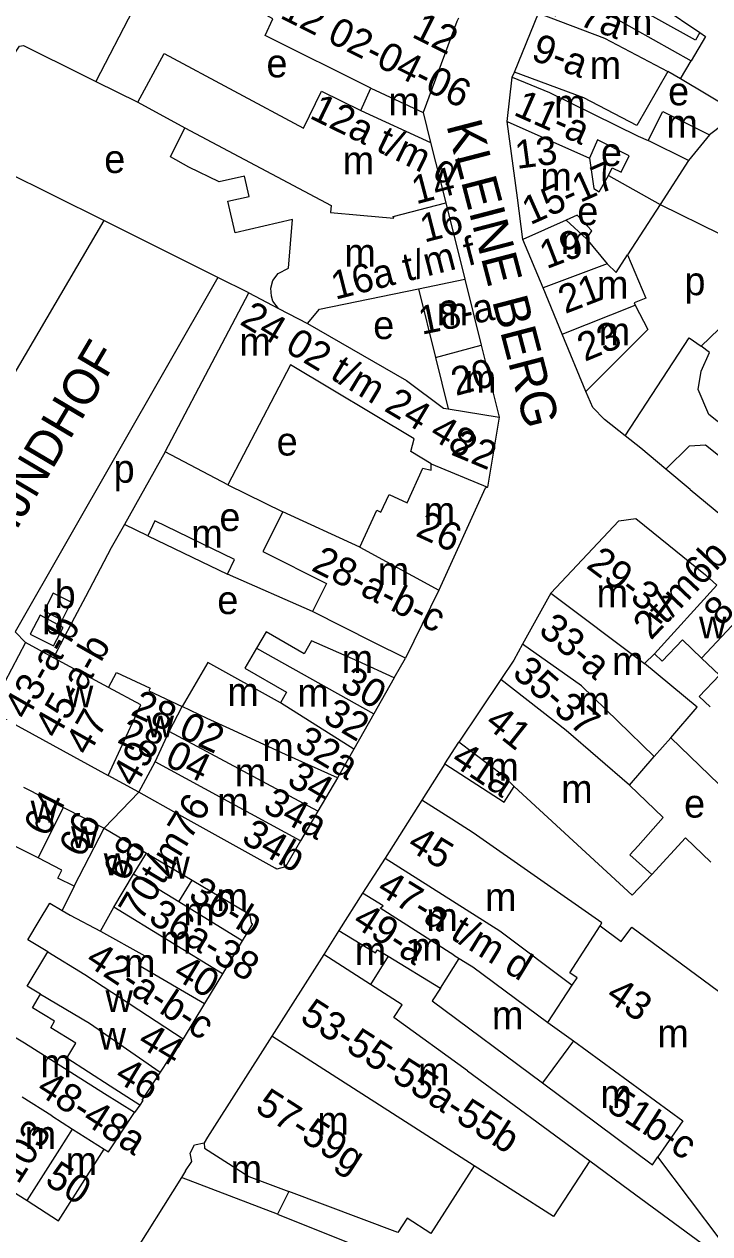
# Model space of a CAD drawing. Extents: x 160673 to 161924, y 382258 to 384145.
# Drawn here: x 161061.5 to 161158.4, y 383019.8 to 383190.7 of the extents above; entities that cross this region are included whole.
import ezdxf

# ---------------------------------------------------------------- set-up
doc = ezdxf.new("R2010")
doc.units = 0
for name, color, linetype in [('BLT_Basislijn', 7, 'Continuous'), ('BLT_Bebouwing', 7, 'Continuous'), ('BLT_Centroide', 7, 'Continuous'), ('BLT_Huisnummer', 7, 'Continuous'), ('BLT_Huisnummer_ tussenligend', 7, 'Continuous'), ('BLT_Huisnummer_reeks', 7, 'Continuous'), ('BLT_Onderdoorgang_en_onderverdeling', 7, 'Continuous'), ('BLT_Onderverdeling_panden', 7, 'Continuous'), ('BLT_Straatnaam', 7, 'Continuous'), ('BLT_Vlakafsluiter', 7, 'Continuous')]:
    doc.layers.add(name, color=color, linetype=linetype)

msp = doc.modelspace()

# ---------------------------------------------------------------- linework, layer by layer
at = {"layer": 'BLT_Basislijn'}
for p, q in [((161076.84, 383192.65), (161071.59, 383182.56)), ((161130.49, 383183.2), (161130.79, 383183.88)), ((161071.59, 383182.56), (161077.56, 383179.63)), ((161072.75, 383162.91), (161058.69, 383169.92)), ((161088.85, 383154.88), (161072.75, 383162.91)), ((161093.23, 383152.7), (161088.85, 383154.88)), ((161157.21, 383145.16), (161166.57, 383154.31)), ((161146.44, 383132.53), (161155.48, 383146.36)), ((161155.48, 383146.36), (161157.21, 383145.16)), ((161158.39, 383144.3), (161157.21, 383145.16)), ((161081.4, 383130.24), (161075.65, 383120.01)), ((161152.18, 383127.82), (161155.52, 383131.12)), ((161090.28, 383125.58), (161098.04, 383121.78)), ((161075.65, 383120.01), (161073.77, 383116.67)), ((161078.95, 383118.39), (161075.65, 383120.01)), ((161073.77, 383116.67), (161070.15, 383109.78)), ((161102.23, 383107.69), (161090.22, 383112.96)), ((161066.27, 383102.41), (161065.61, 383101.15)), ((161113.8, 383098.31), (161115.37, 383101.09)), ((161161.04, 383082.01), (161152.88, 383089.86)), ((161120.94, 383086.18), (161117.7, 383081.03)), ((161077.83, 383037.95), (161077.07, 383036.91)), ((161141.47, 383030.08), (161147.07, 383025.97)), ((161083.7, 383027.74), (161075.08, 383013.99)), ((161097.27, 383022.58), (161108.71, 383018))]:
    msp.add_line(p, q, dxfattribs=at)
for points in [[(161051.19, 383173.08), (161060.81, 383187.57), (161061.4, 383187.65), (161069.83, 383183.47), (161071.59, 383182.56)], [(161162.43, 383178.08), (161158.35, 383175.04)], [(161155.39, 383171.39), (161151.4, 383165.2)], [(161151.4, 383165.2), (161159.81, 383161.05)], [(161072.75, 383162.91), (161043.52, 383113.14), (161040.44, 383114.74)], [(161209.41, 383155.55), (161179.71, 383126.22), (161175.81, 383125.09), (161170.52, 383125.84), (161158.26, 383135.53), (161156.75, 383139.06), (161157.19, 383141.64), (161158.39, 383144.3)], [(161088.85, 383154.88), (161060.21, 383104.82), (161061.64, 383103.3)], [(161146.44, 383132.53), (161143.53, 383134.81), (161141.88, 383136.5), (161140.88, 383138.76)], [(161152.18, 383127.82), (161148.65, 383130.79), (161146.44, 383132.53)], [(161155.52, 383131.12), (161157.8, 383131.22), (161161.28, 383128.45)], [(161155.64, 383124.92), (161152.18, 383127.82)], [(161155.64, 383124.92), (161164.31, 383117.78), (161166.06, 383116.33)], [(161070.15, 383109.78), (161068.6, 383106.83), (161066.57, 383102.99)], [(161066.57, 383102.99), (161066.27, 383102.41)], [(161150.23, 383070.53), (161154.97, 383075.72), (161158.54, 383072.29)], [(161147.07, 383025.97), (161159.71, 383016.67), (161164.6, 383021.65), (161166.91, 383019.35)]]:
    msp.add_lwpolyline(points, dxfattribs=at)
at = {"layer": 'BLT_Bebouwing'}
for p, q in [((161130.79, 383183.88), (161134.17, 383192.23)), ((161129.78, 383176.9), (161130.49, 383183.2)), ((161154.26, 383182.93), (161152.49, 383183.98)), ((161162.43, 383178.08), (161154.26, 383182.93)), ((161109.06, 383178.49), (161110.48, 383181.61)), ((161077.56, 383179.63), (161084.17, 383176.03)), ((161117.87, 383178.2), (161118.94, 383173.94)), ((161131.21, 383166.12), (161129.78, 383176.9)), ((161148.26, 383174.86), (161149.71, 383174.23)), ((161158.35, 383175.04), (161155.39, 383171.39)), ((161118.94, 383173.94), (161121.07, 383165.43)), ((161131.98, 383160.27), (161131.21, 383166.12)), ((161121.07, 383165.43), (161123.77, 383154.64)), ((161151.4, 383165.2), (161146.78, 383158.1)), ((161138.1, 383163), (161140.96, 383160.36)), ((161134.83, 383153.4), (161131.98, 383160.27)), ((161123.77, 383154.64), (161126.09, 383145.34)), ((161088.98, 383144.64), (161093.23, 383152.7)), ((161093.23, 383152.7), (161097.43, 383150.49)), ((161117.21, 383153.29), (161119.61, 383143.57)), ((161137.52, 383146.87), (161134.83, 383153.4)), ((161140.88, 383138.76), (161137.52, 383146.87)), ((161126.09, 383145.34), (161128.64, 383135.15)), ((161081.4, 383130.24), (161088.98, 383144.64)), ((161119.61, 383143.57), (161121.4, 383136.32)), ((161099.14, 383142.56), (161090.28, 383125.58)), ((161128.64, 383135.15), (161126.98, 383125.25)), ((161090.28, 383125.58), (161081.4, 383130.24)), ((161108.95, 383116.78), (161098.04, 383121.78)), ((161078.95, 383118.39), (161090.22, 383112.96)), ((161061.64, 383103.3), (161056.57, 383093.7)), ((161065.61, 383101.15), (161061.64, 383103.3)), ((161149.17, 383100.36), (161150.57, 383101.73)), ((161128.87, 383098.07), (161125.92, 383093.68)), ((161056.57, 383093.7), (161073.37, 383084.54)), ((161110.9, 383093.25), (161108.06, 383088.27)), ((161125.92, 383093.68), (161122.93, 383089.24)), ((161120.94, 383086.18), (161122.93, 383089.24)), ((161150.56, 383087.2), (161152.88, 383089.86)), ((161108.06, 383088.27), (161105.75, 383084.22)), ((161147.05, 383083.15), (161150.56, 383087.2)), ((161077.68, 383082.16), (161073.37, 383084.54)), ((161061.39, 383082.87), (161067.01, 383080.02)), ((161083.39, 383078.96), (161077.68, 383082.16)), ((161117.7, 383081.03), (161112.5, 383072.87)), ((161072.76, 383077.1), (161078.78, 383073.57)), ((161063.43, 383072.88), (161057.76, 383075.74)), ((161078.78, 383073.57), (161085.22, 383069.75)), ((161112.5, 383072.87), (161109.33, 383067.89)), ((161068.55, 383068.88), (161066.83, 383065.47)), ((161109.33, 383067.89), (161105.98, 383062.63)), ((161105.98, 383062.63), (161103.83, 383059.25)), ((161092.31, 383061.17), (161089.51, 383056.53)), ((161103.83, 383059.25), (161096.48, 383047.7)), ((161112.95, 383058.99), (161110.43, 383055.02)), ((161112.95, 383058.99), (161120.33, 383054.5)), ((161089.51, 383056.53), (161086.96, 383052.3)), ((161086.96, 383052.3), (161083.96, 383047.34)), ((161124.16, 383042.8), (161141.47, 383030.08)), ((161054.77, 383028.99), (161061.89, 383024.47)), ((161084.29, 383028.68), (161083.7, 383027.74)), ((161097.27, 383022.58), (161083.7, 383027.74)), ((161098.9, 383025.78), (161097.27, 383022.58)), ((161114.31, 383019.97), (161098.9, 383025.78))]:
    msp.add_line(p, q, dxfattribs=at)
for points in [[(161110.48, 383181.61), (161095.55, 383189.07), (161096.62, 383191.43), (161080.88, 383200.25)], [(161122.86, 383191.51), (161122.64, 383191.04), (161117.87, 383178.2)], [(161077.56, 383179.63), (161081.25, 383186.53), (161100.96, 383175.99), (161103.5, 383181.21), (161109.06, 383178.49)], [(161130.49, 383183.2), (161135.76, 383181.02), (161148.26, 383174.86)], [(161152.49, 383183.98), (161148.1, 383176.35), (161140.59, 383180.25), (161130.79, 383183.88)], [(161149.71, 383174.23), (161151.76, 383178.33), (161158.35, 383175.04)], [(161099.42, 383163.07), (161091.31, 383161.2), (161090.27, 383165.64), (161093.27, 383166.34), (161092.61, 383169.21), (161089.04, 383168.38), (161084.73, 383170.48), (161082.17, 383171.92), (161084.17, 383176.03)], [(161144.07, 383169.29), (161144.63, 383170.37), (161145.89, 383169.76), (161146.99, 383172.05), (161142.52, 383174.32), (161141.42, 383171.74)], [(161155.39, 383171.39), (161149.71, 383174.23)], [(161141.42, 383171.74), (161142.03, 383167.45), (161142.77, 383166.98), (161144.07, 383169.29)], [(161144.07, 383169.29), (161151.4, 383165.2)], [(161097.43, 383150.49), (161096.64, 383151.55), (161096.42, 383152.24), (161096.36, 383153.39), (161096.65, 383154.47), (161097.38, 383155.45), (161098.84, 383156.2), (161099.42, 383163.07)], [(161140.96, 383160.36), (161141.73, 383161.47), (161139.65, 383163.67), (161138.1, 383163)], [(161146.78, 383158.1), (161149.39, 383151.96), (161147.71, 383151.31), (161147.88, 383150.98)], [(161101.53, 383148.39), (161103.25, 383150.41), (161117.21, 383153.29)], [(161147.88, 383150.98), (161149.64, 383147.54)], [(161101.53, 383148.39), (161115.54, 383140.31), (161120.75, 383136.43), (161121.4, 383136.32)], [(161149.64, 383147.54), (161140.88, 383138.76)], [(161116.6, 383132.1), (161099.14, 383142.56)], [(161119.03, 383128.58), (161116.15, 383130.3), (161116.6, 383132.1)], [(161108.95, 383116.78), (161111.35, 383122), (161111.92, 383121.74), (161113.06, 383124.23), (161115.61, 383123.06), (161117.85, 383127.93), (161119.01, 383127.65), (161119.03, 383128.58)], [(161126.98, 383125.25), (161126.63, 383125.12), (161120.12, 383110.73)], [(161098.04, 383121.78), (161095.23, 383116.18), (161104.23, 383111.66), (161102.23, 383107.69)], [(161090.22, 383112.96), (161091.23, 383115.06), (161079.96, 383120.49), (161078.95, 383118.39)], [(161135.95, 383110.3), (161145.53, 383120.49), (161147.95, 383120.82), (161150.4, 383118.88), (161157.82, 383112.89), (161159.39, 383111.43)], [(161120.12, 383110.73), (161115.37, 383101.09)], [(161135.95, 383110.3), (161131.91, 383103.09)], [(161115.37, 383101.09), (161110.9, 383103.33), (161102.23, 383107.69)], [(161113.8, 383098.31), (161108.65, 383100.67), (161102.12, 383103.56), (161101.06, 383101.73), (161095.67, 383104.84), (161094.32, 383102.5)], [(161094.32, 383102.5), (161092.68, 383099.68), (161098.57, 383096.28), (161097.72, 383094.8)], [(161131.91, 383103.09), (161130.7, 383100.84), (161128.87, 383098.07)], [(161150.57, 383101.73), (161151.68, 383100.68), (161154.55, 383103.7), (161157.26, 383101.11)], [(161073.39, 383096.95), (161065.61, 383101.15)], [(161157.26, 383101.11), (161159.79, 383098.71), (161156.9, 383095.68), (161158.44, 383094.23)], [(161073.39, 383096.95), (161074.54, 383099.08), (161079.29, 383096.87), (161079.11, 383096.49), (161083.81, 383094.3)], [(161097.72, 383094.8), (161087.46, 383100.48), (161083.81, 383094.3)], [(161152.88, 383089.86), (161156.62, 383094.17), (161149.17, 383100.36)], [(161113.8, 383098.31), (161111.93, 383095.06), (161110.9, 383093.25)], [(161120.94, 383086.18), (161129.32, 383080.76), (161130.76, 383082.98)], [(161105.75, 383084.22), (161102.97, 383079.48)], [(161130.76, 383082.98), (161147.45, 383067.64), (161150.23, 383070.53)], [(161148.26, 383074.59), (161151.83, 383078.62), (161147.05, 383083.15)], [(161142.9, 383063.27), (161143.15, 383063.73), (161124.96, 383076.42), (161121.92, 383078.35), (161117.7, 383081.03)], [(161067.01, 383080.02), (161072.76, 383077.1)], [(161100.55, 383075.31), (161098.4, 383071.62), (161097.2, 383071.3), (161096.94, 383071.45), (161083.39, 383078.96)], [(161102.97, 383079.48), (161100.55, 383075.31)], [(161150.23, 383070.53), (161147.12, 383073.3), (161148.26, 383074.59)], [(161068.55, 383068.88), (161066.25, 383070.04), (161066.82, 383071.18), (161063.43, 383072.88)], [(161085.22, 383069.75), (161093.35, 383064.93), (161093.59, 383063.7), (161093.77, 383063.59), (161092.31, 383061.17)], [(161064.81, 383059.61), (161061.97, 383061.32), (161063.58, 383063.99), (161065.11, 383066.51), (161066.83, 383065.47)], [(161142.9, 383063.27), (161145.9, 383061.07), (161147.38, 383063.09), (161165.58, 383049.68), (161160.36, 383042.62), (161166.42, 383034.63), (161182.45, 383049.09), (161188.86, 383040.67), (161168.78, 383025.44), (161165.52, 383026.79), (161163.14, 383021.14), (161160.04, 383018.81), (161151.05, 383030.64)], [(161063.79, 383053.62), (161061.88, 383054.75), (161064.81, 383059.61)], [(161124.16, 383042.8), (161113.74, 383050.32), (161114.93, 383052.13), (161110.43, 383055.02)], [(161120.33, 383054.5), (161119.17, 383052.68), (161134.74, 383041.1)], [(161077.83, 383037.95), (161073.63, 383040.66), (161067.5, 383044.62), (161068.78, 383046.74), (161065.22, 383048.89), (161065.78, 383049.83), (161062.65, 383051.72), (161063.79, 383053.62)], [(161077.07, 383036.91), (161072.84, 383039.57), (161061.53, 383046.73), (161051.94, 383052.4), (161048.44, 383047.22)], [(161096.48, 383047.7), (161087.39, 383033.43), (161086.9, 383032.65)], [(161083.96, 383047.34), (161083.23, 383046.12), (161083.06, 383046.22), (161080.7, 383042.63)], [(161080.7, 383042.63), (161078.1, 383038.68), (161078.23, 383038.6), (161077.83, 383037.95)], [(161134.74, 383041.1), (161150.3, 383029.52), (161151.05, 383030.64)], [(161072.77, 383031.74), (161073.39, 383031.36), (161077.07, 383036.91)], [(161084.29, 383028.68), (161085.19, 383029.99), (161084.92, 383031.18), (161085.56, 383032.36), (161086.9, 383032.65)], [(161061.89, 383024.47), (161066.34, 383021.63), (161072.77, 383031.74)], [(161125.11, 383029.37), (161118.99, 383019.85), (161115.63, 383022.01), (161114.31, 383019.97)], [(161141.47, 383030.08), (161136.3, 383022.23), (161125.11, 383029.37)]]:
    msp.add_lwpolyline(points, dxfattribs=at)
for points in [[(161064.29, 383107.78), (161066.83, 383106.48), (161068.12, 383109.02), (161065.59, 383110.31)], [(161063.72, 383107.16), (161062.34, 383104.49), (161065.62, 383102.83), (161066.97, 383105.42)]]:
    msp.add_lwpolyline(points, close=True, dxfattribs=at)
at = {"layer": 'BLT_Onderdoorgang_en_onderverdeling'}
msp.add_lwpolyline([(161086.9, 383032.65), (161086.98, 383031.9), (161093.26, 383027.9), (161098.9, 383025.78)], dxfattribs=at)
at = {"layer": 'BLT_Onderverdeling_panden'}
for p, q in [((161154.26, 383182.93), (161155.76, 383185.47)), ((161110.48, 383181.61), (161117.87, 383178.2)), ((161109.06, 383178.49), (161118.94, 383173.94)), ((161084.17, 383176.03), (161104.86, 383165.03)), ((161129.78, 383176.9), (161141.42, 383171.74)), ((161104.86, 383165.03), (161104.8, 383164.07)), ((161104.8, 383164.07), (161109, 383163.68)), ((161138.1, 383163), (161131.98, 383160.27)), ((161140.96, 383160.36), (161143.9, 383156.79)), ((161143.9, 383156.79), (161134.83, 383153.4)), ((161117.21, 383153.29), (161123.77, 383154.64)), ((161097.43, 383150.49), (161101.53, 383148.39)), ((161137.52, 383146.87), (161147.88, 383150.98)), ((161119.61, 383143.57), (161126.09, 383145.34)), ((161121.4, 383136.32), (161128.64, 383135.15)), ((161119.03, 383128.58), (161126.98, 383125.25)), ((161108.95, 383116.78), (161120.12, 383110.73)), ((161159.39, 383111.43), (161150.57, 383101.73)), ((161135.95, 383110.3), (161149.17, 383100.36)), ((161157.26, 383101.11), (161163.35, 383107.64)), ((161094.32, 383102.5), (161110.9, 383093.25)), ((161138.11, 383090.91), (161128.87, 383098.07)), ((161081.99, 383090.76), (161083.81, 383094.3)), ((161087.36, 383092.6), (161083.81, 383094.3)), ((161108.06, 383088.27), (161097.72, 383094.8)), ((161079.98, 383086.48), (161081.99, 383090.76)), ((161102.97, 383079.48), (161081.99, 383090.76)), ((161147.05, 383083.15), (161138.11, 383090.91)), ((161077.68, 383082.16), (161079.98, 383086.48)), ((161100.55, 383075.31), (161079.98, 383086.48)), ((161063.43, 383072.88), (161067.01, 383080.02)), ((161068.55, 383068.88), (161072.76, 383077.1)), ((161076.95, 383070.58), (161078.78, 383073.57)), ((161074.13, 383065.95), (161076.95, 383070.58)), ((161083.35, 383066.66), (161076.95, 383070.58)), ((161083.35, 383066.66), (161085.22, 383069.75)), ((161092.31, 383061.17), (161083.35, 383066.66)), ((161072.27, 383062.54), (161074.13, 383065.95)), ((161120.33, 383054.5), (161122.99, 383058.68)), ((161135.49, 383049.65), (161138.97, 383054.91)), ((161135.49, 383049.65), (161139.15, 383047.03)), ((161125.11, 383029.37), (161096.48, 383047.7)), ((161139.15, 383047.03), (161134.74, 383041.1)), ((161065.38, 383036.46), (161061.21, 383039.1)), ((161065.38, 383036.46), (161068.32, 383034.57)), ((161066.52, 383031.74), (161068.32, 383034.57)), ((161068.32, 383034.57), (161072.77, 383031.74)), ((161061.89, 383024.47), (161066.52, 383031.74))]:
    msp.add_line(p, q, dxfattribs=at)
for points in [[(161139.8, 383204.47), (161148.22, 383200.28), (161153.89, 383196.39), (161151.66, 383193.08), (161157, 383189.47)], [(161157, 383189.47), (161156.39, 383188.42), (161146.04, 383194.19), (161136.87, 383198.65)], [(161135.43, 383195.33), (161145.02, 383191.5), (161155.76, 383185.47)], [(161134.17, 383192.23), (161143.54, 383188.71), (161152.49, 383183.98)], [(161157, 383189.47), (161157.81, 383188.92), (161155.76, 383185.47)], [(161109, 383163.68), (161113.76, 383163.24), (161113.65, 383163.49), (161121.07, 383165.43)], [(161143.9, 383156.79), (161145.18, 383155.59), (161146.78, 383158.1)], [(161150.56, 383087.2), (161140.25, 383097.18), (161131.91, 383103.09)], [(161073.37, 383084.54), (161077.96, 383094.49), (161073.39, 383096.95)], [(161105.75, 383084.22), (161098.43, 383087.48), (161090.54, 383091.1), (161087.36, 383092.6)], [(161130.76, 383082.98), (161129.27, 383084.44), (161122.93, 383089.24)], [(161112.5, 383072.87), (161128.71, 383062.6), (161138.97, 383054.91)], [(161122.23, 383059.15), (161111.82, 383065.77), (161112.22, 383066.12), (161109.33, 383067.89)], [(161066.83, 383065.47), (161067.98, 383064.78), (161072.27, 383062.54)], [(161089.51, 383056.53), (161074.13, 383065.95)], [(161138.97, 383054.91), (161139.65, 383055.96), (161138.61, 383056.66), (161142.9, 383063.27)], [(161072.27, 383062.54), (161078.54, 383059.07), (161077.7, 383057.72), (161086.96, 383052.3)], [(161105.98, 383062.63), (161111.16, 383059.46), (161111.44, 383059.92), (161112.95, 383058.99)], [(161064.81, 383059.61), (161070.06, 383056.43), (161083.96, 383047.34)], [(161110.43, 383055.02), (161103.83, 383059.25)], [(161122.23, 383059.15), (161122.99, 383058.68)], [(161122.99, 383058.68), (161124.43, 383057.79), (161124.91, 383057.5), (161135.49, 383049.65)], [(161063.79, 383053.62), (161070.72, 383049.53), (161080.7, 383042.63)], [(161139.15, 383047.03), (161154.61, 383035.76), (161151.05, 383030.64)]]:
    msp.add_lwpolyline(points, dxfattribs=at)
at = {"layer": 'BLT_Vlakafsluiter'}
msp.add_line((161072.76, 383077.1), (161077.68, 383082.16), dxfattribs=at)

# ---------------------------------------------------------------- texts
at = {"layer": 'BLT_Centroide'}
for s, p in [('m', (161145.84, 383189.12)), ('e', (161095.73, 383183.15)), ('m', (161141.42, 383182.91)), ('m', (161112.97, 383177.78)), ('e', (161152.52, 383179.2)), ('m', (161136.41, 383177.47)), ('m', (161152.28, 383174.63)), ('e', (161072.79, 383169.64)), ('m', (161106.5, 383169.44)), ('e', (161143.01, 383170.62)), ('m', (161134.46, 383167.13)), ('e', (161139.67, 383162.28)), ('m', (161137.32, 383158.19)), ('m', (161106.73, 383156.39)), ('p', (161154.82, 383152.38)), ('m', (161142.45, 383151.88)), ('m', (161119.79, 383148.12)), ('e', (161110.82, 383146.18)), ('m', (161091.89, 383143.83)), ('m', (161142.7, 383145.28)), ('m', (161123.78, 383138.61)), ('e', (161097.17, 383129.73)), ('p', (161074.12, 383125.89)), ('m', (161117.97, 383119.91)), ('e', (161089.08, 383119.06)), ('m', (161085.09, 383116.72)), ('m', (161111.46, 383111.44)), ('b', (161065.78, 383108.17)), ('m', (161142.4, 383108.3)), ('e', (161088.78, 383107.33)), ('b', (161064.03, 383104.48)), ('w', (161156.89, 383103.9)), ('m', (161106.36, 383099.03)), ('m', (161144.58, 383098.75)), ('w', (161067.38, 383094.16)), ('m', (161090.19, 383094.37)), ('m', (161100.09, 383094.24)), ('m', (161139.85, 383093.12)), ('w', (161078.79, 383089.91)), ('m', (161095.13, 383086.56)), ('m', (161126.95, 383083.79)), ('m', (161091.24, 383083)), ('m', (161137.39, 383080.66)), ('m', (161088.76, 383078.84)), ('w', (161062.39, 383077.89)), ('e', (161154.78, 383078.58)), ('w', (161068.09, 383074.3)), ('w', (161072.73, 383070.44)), ('w', (161081.02, 383069.97)), ('m', (161088.67, 383065.38)), ('m', (161126.62, 383065.38)), ('m', (161083.98, 383063.34)), ('m', (161118.32, 383062.57)), ('m', (161080.67, 383059.38)), ('m', (161116.16, 383058.35)), ('m', (161108.21, 383057.77)), ('m', (161075.59, 383056.06)), ('w', (161072.97, 383051.12)), ('m', (161127.6, 383048.69)), ('w', (161072.02, 383045.81)), ('m', (161150.99, 383046.12)), ('m', (161063.76, 383041.91)), ('m', (161117.16, 383040.75)), ('m', (161142.95, 383037.58)), ('m', (161102.92, 383033.78)), ('m', (161061.55, 383031.78)), ('m', (161067.33, 383028.09)), ('m', (161090.66, 383026.96))]:
    msp.add_text(s, height=4, dxfattribs=at).set_placement(p)
at = {"layer": 'BLT_Huisnummer'}
for s, rotation, p in [('11-a', 336.085, (161130.51, 383177.9)), ('19', 21.1064, (161135.33, 383156.03)), ('21', 21.1064, (161137.96, 383149.71)), ('23', 22.4756, (161140.73, 383142.95)), ('26', 335.3626, (161116.66, 383118.46)), ('8', 47.025, (161160.1, 383105.45)), ('30', 329.992, (161105.95, 383096.76)), ('32', 329.493, (161103.53, 383092.24)), ('41', 321.512, (161126.43, 383091.62)), ('32a', 329.493, (161099.51, 383088.34)), ('41a', 326.512, (161121.64, 383086.24)), ('34', 330.033, (161098.43, 383083.32)), ('64', 62.8678, (161064.74, 383075.67)), ('34a', 332.0038, (161095.04, 383079.55)), ('34b', 330.0301, (161092, 383075.17)), ('45', 328.5688, (161115.44, 383074.23)), ('68', 58.8855, (161075.79, 383069.32)), ('40', 328.883, (161082.34, 383056.03)), ('43', 325.512, (161143.52, 383052.97)), ('44', 328.8849, (161077.32, 383046.42)), ('50', 327.538, (161064.22, 383026.93))]:
    msp.add_text(s, height=4, rotation=rotation, dxfattribs=at).set_placement(p)
at = {"layer": 'BLT_Huisnummer_ tussenligend'}
for s, rotation, p in [('66', 62.8678, (161069.73, 383072.73)), ('46', 328.8849, (161074.07, 383041.54))]:
    msp.add_text(s, height=4, rotation=rotation, dxfattribs=at).set_placement(p)
at = {"layer": 'BLT_Huisnummer_reeks'}
for s, rotation, p in [('7-7a', 339.4172, (161135.29, 383192.25)), ('12 02-04-06', 333.4426, (161097.49, 383191.61)), ('12', 333.4426, (161116.12, 383188.93)), ('9-a', 339.6698, (161132.98, 383185.7)), ('12a t/m d', 333.9728, (161101.67, 383177.46)), ('13', 7.5322, (161131.14, 383170.21)), ('15-17', 24.0728, (161133.02, 383162.24)), ('14', 14.7227, (161116.88, 383165.2)), ('16', 14.2794, (161118.04, 383159.8)), ('16a t/m f', 14.2794, (161105.46, 383151.72)), ('24 02 t/m 24 48', 329.0953, (161091.8, 383148.35)), ('18-a', 11.6193, (161117.68, 383146.78)), ('20', 15.3332, (161122.49, 383138.12)), ('22', 337.2892, (161121.67, 383129.91)), ('28-a-b-c', 333.324, (161101.92, 383113.57)), ('29-31', 323.0837, (161140.79, 383113.98)), ('2t/m6b', 46.7678, (161150.09, 383103.54)), ('43-a-b', 60.3796, (161061.84, 383092.22)), ('33-a', 320.2186, (161134.03, 383104.75)), ('45-a-b', 60.3796, (161066.15, 383089.55)), ('35-37', 319.035, (161130.31, 383098.74)), ('28 02', 335.1622, (161076.37, 383093.17)), ('47', 60.3796, (161070.52, 383087.18)), ('28 04', 334.4439, (161074.46, 383089.27)), ('49', 60.3796, (161077.14, 383082.74)), ('70t/m76', 58.8951, (161078, 383063.8)), ('36-b', 328.8898, (161084.5, 383067.1)), ('47-a t/m d', 328.5688, (161111.14, 383067.96)), ('36a-38', 328.8898, (161078.84, 383063.92)), ('49-a', 327.3042, (161107.71, 383063.42)), ('42-a-b-c', 326.8026, (161069.95, 383057.95)), ('53-55-55a-55b', 327.3665, (161100.28, 383049.9)), ('48-48a', 327.4831, (161063.01, 383039.72)), ('57-59g', 327.3667, (161093.94, 383037.21)), ('51b-c', 327.3042, (161143.62, 383037.35)), ('103', 57.5394, (161060.62, 383026.64))]:
    msp.add_text(s, height=4, rotation=rotation, dxfattribs=at).set_placement(p)
at = {"layer": 'BLT_Straatnaam'}
for s, rotation, p in [('KLEINE BERG', 284.6256, (161121.14, 383176.4)), ('SPIJNDHOF', 59.3864, (161055.8, 383111.35))]:
    msp.add_text(s, height=5, rotation=rotation, dxfattribs=at).set_placement(p)

doc.saveas('drawing.dxf')
